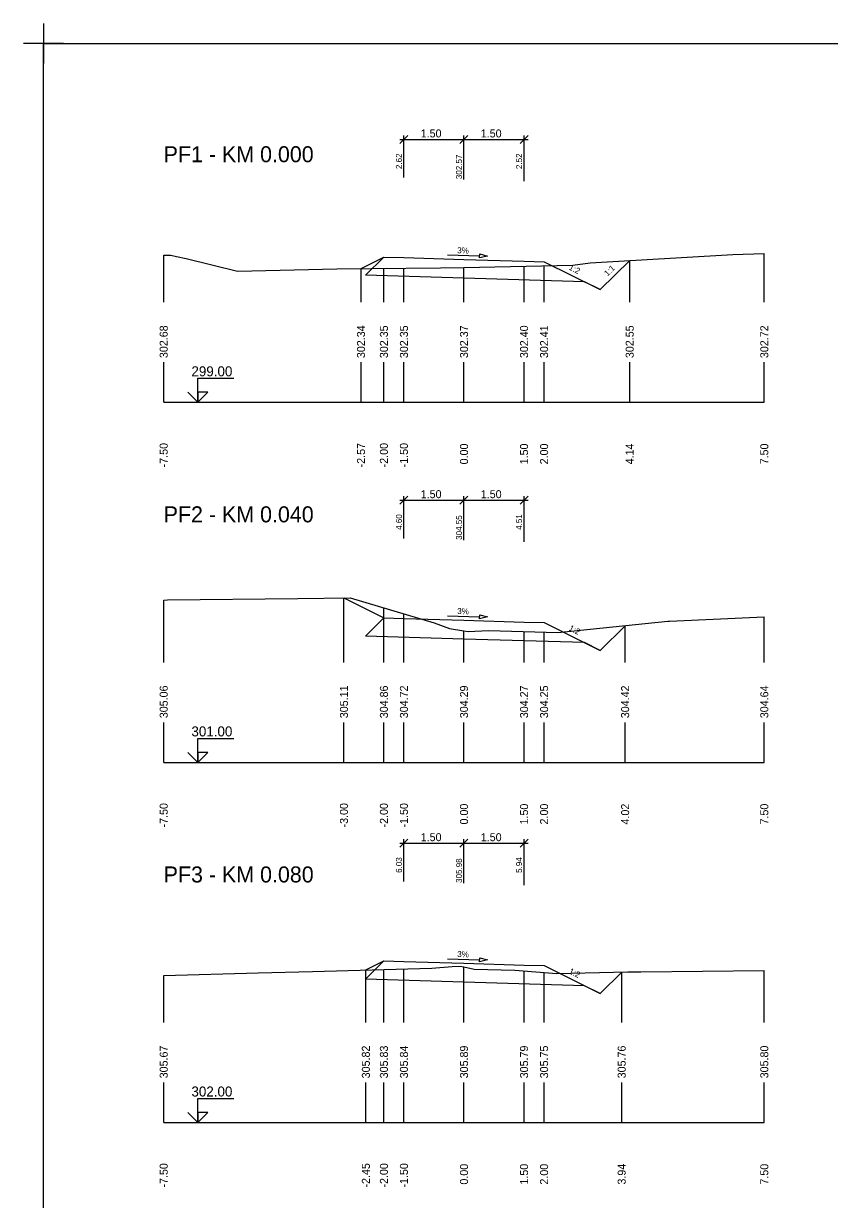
# Model space of a CAD drawing. Extents: x -5 to 1265, y -2 to 602.
# Drawn here: x -5 to 196.3, y 307.8 to 601.7 of the extents above; entities that cross this region are included whole.
import ezdxf

# ---------------------------------------------------------------- set-up
doc = ezdxf.new("R2010")
doc.units = 0
for name, color, linetype in [('KOTA', 7, 'Continuous'), ('KOTA_DELKY', 7, 'Continuous'), ('KOTA_DELKY_CONT', 7, 'Continuous'), ('NS_TELESO_VOZOVKY', 7, 'Continuous'), ('NS_V_PF', 7, 'Continuous'), ('REZY_PF_PUVODNI', 7, 'Continuous'), ('SESTAVY_REZU_PF', 7, 'Continuous'), ('SKLON', 7, 'Continuous'), ('SVK', 7, 'Continuous')]:
    doc.layers.add(name, color=color, linetype=linetype)

msp = doc.modelspace()

# ---------------------------------------------------------------- linework, layer by layer
for p, q in [((0, 601.67), (0, 591.67)), ((0, 601.67), (0, 591.67)), ((0, 601.67), (0, 591.67)), ((0, 601.67), (0, 591.67)), ((0, 601.67), (0, 591.67)), ((0, 601.67), (0, 591.67)), ((0, 601.67), (0, 591.67)), ((0, 601.67), (0, 591.67)), ((0, 601.67), (0, 591.67)), ((0, 601.67), (0, 591.67)), ((0, 601.67), (0, 591.67)), ((0, 601.67), (0, 591.67)), ((0, 601.67), (0, 591.67)), ((0, 601.67), (0, 591.67)), ((0, 601.67), (0, 591.67)), ((0, 601.67), (0, 591.67)), ((0, 601.67), (0, 591.67)), ((0, 601.67), (0, 591.67)), ((0, 601.67), (0, 591.67)), ((0, 601.67), (0, 591.67)), ((0, 601.67), (0, 591.67)), ((0, 601.67), (0, 591.67)), ((0, 601.67), (0, 591.67)), ((0, 601.67), (0, 591.67)), ((0, 601.67), (0, 591.67)), ((0, 601.67), (0, 591.67)), ((0, 601.67), (0, 591.67)), ((0, 601.67), (0, 591.67)), ((0, 601.67), (0, 591.67)), ((0, 601.67), (0, 591.67)), ((0, 601.67), (0, 591.67)), ((0, 601.67), (0, 591.67)), ((0, 601.67), (0, 591.67)), ((0, 601.67), (0, 591.67)), ((0, 601.67), (0, 591.67)), ((0, 601.67), (0, 591.67)), ((5, 596.67), (-5, 596.67)), ((5, 596.67), (-5, 596.67)), ((5, 596.67), (-5, 596.67)), ((5, 596.67), (-5, 596.67)), ((5, 596.67), (-5, 596.67)), ((5, 596.67), (-5, 596.67)), ((5, 596.67), (-5, 596.67)), ((5, 596.67), (-5, 596.67)), ((5, 596.67), (-5, 596.67)), ((5, 596.67), (-5, 596.67)), ((5, 596.67), (-5, 596.67)), ((5, 596.67), (-5, 596.67)), ((5, 596.67), (-5, 596.67)), ((5, 596.67), (-5, 596.67)), ((5, 596.67), (-5, 596.67)), ((5, 596.67), (-5, 596.67)), ((5, 596.67), (-5, 596.67)), ((5, 596.67), (-5, 596.67)), ((5, 596.67), (-5, 596.67)), ((5, 596.67), (-5, 596.67)), ((5, 596.67), (-5, 596.67)), ((5, 596.67), (-5, 596.67)), ((5, 596.67), (-5, 596.67)), ((5, 596.67), (-5, 596.67)), ((5, 596.67), (-5, 596.67)), ((5, 596.67), (-5, 596.67)), ((5, 596.67), (-5, 596.67)), ((5, 596.67), (-5, 596.67)), ((5, 596.67), (-5, 596.67)), ((5, 596.67), (-5, 596.67)), ((5, 596.67), (-5, 596.67)), ((5, 596.67), (-5, 596.67)), ((5, 596.67), (-5, 596.67)), ((5, 596.67), (-5, 596.67)), ((5, 596.67), (-5, 596.67)), ((5, 596.67), (-5, 596.67))]:
    msp.add_line(p, q)
msp.add_lwpolyline([(0, 596.67), (1260, 596.67), (1260, 2.67), (0, 2.67)], close=True)
at = {"layer": 'KOTA'}
for points in [[(38.51, 507), (36.01, 509.5), (38.51, 507), (38.51, 513), (47.51, 513)], [(38.51, 507), (41.01, 509.5), (38.51, 509.5), (38.51, 507)], [(38.51, 507), (41.01, 509.5), (38.51, 509.5)], [(38.51, 417), (36.01, 419.5), (38.51, 417), (38.51, 423), (47.51, 423)], [(38.51, 417), (41.01, 419.5), (38.51, 419.5), (38.51, 417)], [(38.51, 417), (41.01, 419.5), (38.51, 419.5)], [(38.51, 327), (36.01, 329.5), (38.51, 327), (38.51, 333), (47.51, 333)], [(38.51, 327), (41.01, 329.5), (38.51, 329.5), (38.51, 327)], [(38.51, 327), (41.01, 329.5), (38.51, 329.5)]]:
    msp.add_lwpolyline(points, dxfattribs=at)
at = {"layer": 'KOTA_DELKY'}
for points in [[(89, 571.7), (91, 573.7)], [(90, 563.15), (90, 573.7)], [(104, 571.7), (106, 573.7)], [(104, 571.7), (106, 573.7)], [(105, 562.7), (105, 573.7)], [(105, 562.7), (105, 573.7)], [(119, 571.7), (121, 573.7)], [(120, 562.25), (120, 573.7)], [(89, 572.7), (106, 572.7)], [(104, 572.7), (121, 572.7)], [(89, 481.54), (91, 483.54)], [(89, 482.54), (106, 482.54)], [(90, 472.99), (90, 483.54)], [(104, 481.54), (106, 483.54)], [(104, 481.54), (106, 483.54)], [(104, 482.54), (121, 482.54)], [(105, 472.54), (105, 483.54)], [(105, 472.54), (105, 483.54)], [(119, 481.54), (121, 483.54)], [(120, 472.09), (120, 483.54)], [(89, 395.81), (91, 397.81)], [(89, 396.81), (106, 396.81)], [(90, 387.26), (90, 397.81)], [(104, 395.81), (106, 397.81)], [(104, 395.81), (106, 397.81)], [(104, 396.81), (121, 396.81)], [(105, 386.81), (105, 397.81)], [(105, 386.81), (105, 397.81)], [(119, 395.81), (121, 397.81)], [(120, 386.36), (120, 397.81)]]:
    msp.add_lwpolyline(points, dxfattribs=at)
at = {"layer": 'NS_TELESO_VOZOVKY'}
for points in [[(105, 542.7), (120, 542.25), (125, 542.1), (139.01, 535.17), (135.11, 537.1), (105, 538), (80.44, 538.74), (85, 543.3), (90, 543.15), (105, 542.7)], [(105, 452.54), (120, 452.09), (125, 451.94), (139.01, 445.01), (135.11, 446.94), (105, 447.84), (80.44, 448.58), (85, 453.14), (90, 452.99), (105, 452.54)], [(105, 366.81), (120, 366.36), (125, 366.21), (139.01, 359.27), (135.11, 361.2), (105, 362.11), (80.44, 362.84), (85, 367.41), (90, 367.26), (105, 366.81)]]:
    msp.add_lwpolyline(points, dxfattribs=at)
at = {"layer": 'NS_V_PF'}
for points in [[(79.28, 540.44), (85, 543.3), (90, 543.15), (105, 542.7), (120, 542.25), (125, 542.1), (139.01, 535.17), (146.38, 542.46)], [(75.02, 458.13), (85, 453.14), (90, 452.99), (105, 452.54), (120, 452.09), (125, 451.94), (139.01, 445.01), (145.24, 451.17)], [(80.49, 365.15), (85, 367.41), (90, 367.26), (105, 366.81), (120, 366.36), (125, 366.21), (139.01, 359.27), (144.38, 364.59)]]:
    msp.add_lwpolyline(points, dxfattribs=at)
at = {"layer": 'REZY_PF_PUVODNI'}
for points in [[(30, 543.81), (31.76, 543.8), (33.2, 543.47), (35.63, 542.9), (48.46, 539.76), (73.22, 540.39), (81.88, 540.46), (99.16, 540.57), (105, 540.7), (132.21, 541.31), (136.52, 541.88), (172.17, 543.98), (180, 544.15)], [(30, 457.59), (30.98, 457.61), (63.51, 458), (76.61, 458.15), (97.54, 451.91), (101.42, 450.45), (105, 449.89), (105, 449.89), (106.01, 449.73), (111.08, 449.98), (128.42, 449.43), (155.93, 452.28), (156.34, 452.32), (180, 453.36)], [(30, 363.71), (53.63, 364.4), (67.13, 364.78), (96.93, 365.61), (102.08, 365.97), (104.02, 366.11), (105, 365.9), (105, 365.9), (107.58, 365.33), (117.66, 365.06), (128.18, 364.26), (145.91, 364.62), (149.16, 364.66), (180, 364.99)]]:
    msp.add_lwpolyline(points, dxfattribs=at)
at = {"layer": 'SESTAVY_REZU_PF'}
for points in [[(30, 507), (180, 507)], [(30, 417), (180, 417)], [(30, 327), (180, 327)]]:
    msp.add_lwpolyline(points, dxfattribs=at)
at = {"layer": 'SKLON'}
for points in [[(100.92, 543.82), (108.91, 543.58)], [(108.93, 544.08), (110.91, 543.52), (108.9, 543.08), (108.93, 544.08)], [(100.92, 453.66), (108.91, 453.42)], [(108.93, 453.92), (110.91, 453.36), (108.9, 452.92), (108.93, 453.92)], [(100.92, 367.93), (108.91, 367.69)], [(108.93, 368.19), (110.91, 367.63), (108.9, 367.19), (108.93, 368.19)]]:
    msp.add_lwpolyline(points, dxfattribs=at)
for points in [[(108.93, 544.08), (110.91, 543.52), (108.9, 543.08)], [(108.93, 453.92), (110.91, 453.36), (108.9, 452.92)], [(108.93, 368.19), (110.91, 367.63), (108.9, 367.19)]]:
    msp.add_lwpolyline(points, close=True, dxfattribs=at)
at = {"layer": 'SVK'}
for points in [[(30, 532), (30, 543.81)], [(180, 532), (180, 544.15)], [(120, 532), (120, 541.04)], [(125, 532), (125, 541.15)], [(146.38, 532), (146.38, 542.46)], [(79.28, 532), (79.28, 540.44)], [(85, 532), (85, 540.48)], [(90, 532), (90, 540.51)], [(105, 532), (105, 540.7)], [(30, 507), (30, 517)], [(79.28, 507), (79.28, 517)], [(85, 507), (85, 517)], [(90, 507), (90, 517)], [(105, 507), (105, 517)], [(120, 507), (120, 517)], [(125, 507), (125, 517)], [(146.38, 507), (146.38, 517)], [(180, 507), (180, 517)], [(30, 442), (30, 457.59)], [(75.02, 442), (75.02, 458.13)], [(85, 442), (85, 455.65)], [(90, 442), (90, 454.16)], [(180, 442), (180, 453.36)], [(105, 442), (105, 449.89)], [(120, 442), (120, 449.69)], [(145.24, 442), (145.24, 451.17)], [(125, 442), (125, 449.54)], [(30, 417), (30, 427)], [(75.02, 417), (75.02, 427)], [(85, 417), (85, 427)], [(90, 417), (90, 427)], [(105, 417), (105, 427)], [(120, 417), (120, 427)], [(125, 417), (125, 427)], [(145.24, 417), (145.24, 427)], [(180, 417), (180, 427)], [(80.49, 352), (80.49, 365.15)], [(85, 352), (85, 365.28)], [(90, 352), (90, 365.42)], [(105, 352), (105, 365.9)], [(120, 352), (120, 364.89)], [(125, 352), (125, 364.51)], [(144.38, 352), (144.38, 364.59)], [(180, 352), (180, 364.99)], [(30, 352), (30, 363.71)], [(30, 327), (30, 337)], [(80.49, 327), (80.49, 337)], [(85, 327), (85, 337)], [(90, 327), (90, 337)], [(105, 327), (105, 337)], [(120, 327), (120, 337)], [(125, 327), (125, 337)], [(144.38, 327), (144.38, 337)], [(180, 327), (180, 337)]]:
    msp.add_lwpolyline(points, dxfattribs=at)

# ---------------------------------------------------------------- texts
at = {"layer": 'KOTA'}
for s, p in [('299.00', (36.93, 513.5)), ('301.00', (36.93, 423.5)), ('302.00', (36.93, 333.5))]:
    msp.add_text(s, height=2.5, dxfattribs=at).set_placement(p)
at = {"layer": 'KOTA_DELKY'}
for p in [(94.19, 573.2), (109.19, 573.2), (94.19, 483.04), (109.19, 483.04), (94.19, 397.31), (109.19, 397.31)]:
    msp.add_text('1.50', height=2, dxfattribs=at).set_placement(p)
at = {"layer": 'KOTA_DELKY_CONT'}
for s, p in [('2.62', (89.5, 565.29)), ('302.57', (104.5, 562.78)), ('2.52', (119.5, 565.29)), ('4.60', (89.5, 475.13)), ('304.55', (104.5, 472.62)), ('4.51', (119.5, 475.13)), ('6.03', (89.5, 389.39)), ('305.98', (104.5, 386.88)), ('5.94', (119.5, 389.39))]:
    msp.add_text(s, height=1.5, rotation=90, dxfattribs=at).set_placement(p)
at = {"layer": 'SESTAVY_REZU_PF'}
for s, p in [('PF1 - KM 0.000', (30, 567)), ('PF2 - KM 0.040', (30, 477)), ('PF3 - KM 0.080', (30, 387))]:
    msp.add_text(s, height=4, dxfattribs=at).set_placement(p)
at = {"layer": 'SKLON'}
for s, rotation, p in [('3%', 358.2816, (103.29, 544.25)), ('1:2', 333.679, (131.04, 540.23)), ('1:1', 44.7149, (140.87, 538.41)), ('3%', 358.2816, (103.29, 454.09)), ('1:2', 333.679, (131.04, 450.07)), ('3%', 358.2816, (103.29, 368.36)), ('1:2', 333.679, (131.04, 364.33))]:
    msp.add_text(s, height=1.5, rotation=rotation, dxfattribs=at).set_placement(p)
at = {"layer": 'SVK'}
for s, p in [(' 302.68', (31, 517.3)), (' 302.34', (80.28, 517.3)), (' 302.35', (86, 517.3)), (' 302.35', (91, 517.3)), (' 302.37', (106, 517.3)), (' 302.40', (121, 517.3)), (' 302.41', (126, 517.3)), (' 302.55', (147.38, 517.3)), (' 302.72', (181, 517.3)), (' -7.50', (31, 490)), (' -2.57', (80.28, 490)), (' -2.00', (86, 490)), (' -1.50', (91, 490)), ('  0.00', (106, 490)), ('  1.50', (121, 490)), ('  2.00', (126, 490)), ('  4.14', (147.38, 490)), ('  7.50', (181, 490)), (' 305.06', (31, 427.3)), (' 305.11', (76.02, 427.3)), (' 304.86', (86, 427.3)), (' 304.72', (91, 427.3)), (' 304.29', (106, 427.3)), (' 304.27', (121, 427.3)), (' 304.25', (126, 427.3)), (' 304.42', (146.24, 427.3)), (' 304.64', (181, 427.3)), (' -7.50', (31, 400)), (' -3.00', (76.02, 400)), (' -2.00', (86, 400)), (' -1.50', (91, 400)), ('  0.00', (106, 400)), ('  1.50', (121, 400)), ('  2.00', (126, 400)), ('  4.02', (146.24, 400)), ('  7.50', (181, 400)), (' 305.67', (31, 337.3)), (' 305.82', (81.49, 337.3)), (' 305.83', (86, 337.3)), (' 305.84', (91, 337.3)), (' 305.89', (106, 337.3)), (' 305.79', (121, 337.3)), (' 305.75', (126, 337.3)), (' 305.76', (145.38, 337.3)), (' 305.80', (181, 337.3)), (' -7.50', (31, 310)), (' -2.45', (81.49, 310)), (' -2.00', (86, 310)), (' -1.50', (91, 310)), ('  0.00', (106, 310)), ('  1.50', (121, 310)), ('  2.00', (126, 310)), ('  3.94', (145.38, 310)), ('  7.50', (181, 310))]:
    msp.add_text(s, height=2, rotation=90, dxfattribs=at).set_placement(p)

doc.saveas('drawing.dxf')
